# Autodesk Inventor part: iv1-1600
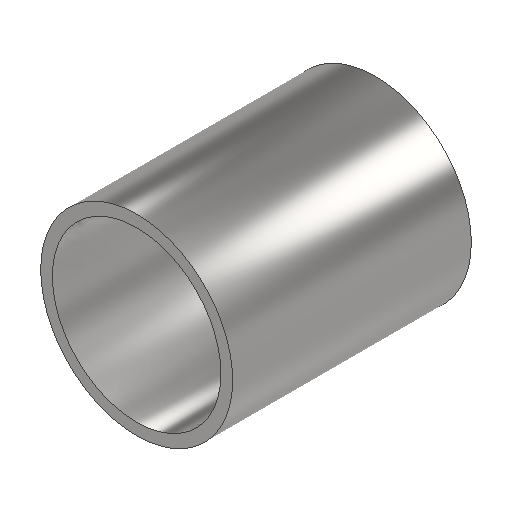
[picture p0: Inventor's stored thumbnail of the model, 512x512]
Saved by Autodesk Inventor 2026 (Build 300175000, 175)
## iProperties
Created: 2022-01
Part Number: iv1-1600
Material: Steel, Mild
Document SubType Name: Modeling
Designer: Lars Bertram Pedersen
Density: 7.85 g/cm^3
Appearance: Semi-Polished
Mass: 243.221 g
Surface Area: 211.19 cm^2
Volume: 30.9836 cm^3
Author: Lars Bertram Pedersen
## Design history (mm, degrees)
sketch "Sketch1"
  geometry: C1 r 24.58 at (0, 0); 1 further point
  constraints: 1 centre point, 1 coincident
  dimensions: "d0" = 49.16 diameter of C1 (= Yderdiameter)
extrude "Extrusion1" new body sketch "Sketch1" distance "d1" = 61.13 (= Cylinderhøjde); taper "d2" = 0 deg
sketch "Sketch2"
  geometry: C1 r 21.58 at (0, 0); 1 further point
  constraints: 1 centre point, 1 coincident
  dimensions: "d3" = 43.16 diameter of C1 (= Inderdiameter)
extrude "Extrusion2" cut sketch "Sketch2" distance "d4" = 58.13 (= Hulhøjde); taper "d5" = 0 deg
body "Solid1"
other parameters: "Yderdiameter" = 49.16 [user parameter; used in 1 equation term], "Cylinderhøjde" = 61.13 [user parameter; used in 1 equation term], "Inderdiameter" = 43.16 [user parameter; used in 1 equation term], "Hulhøjde" = 58.13 [user parameter; used in 1 equation term]
